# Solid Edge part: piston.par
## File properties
Author: Vicky Raina
Template: normal.par
Last saved by: Robert a Rhodes jr
Revision: 8
Application: Solid Edge
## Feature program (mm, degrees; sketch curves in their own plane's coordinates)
sketch for "unnamed RevolvedProtrusion 1" plane through (0, 0, 0) normal (0, -1, 0) x-axis (1, 0, 0)
  line (0, 27.2252) -> (0, 16)
  line (0, 16) -> (37, 16)
  line (37, 16) -> (37, -4)
  line (37, -4) -> (38.5, -4)
  line (38.5, -4) -> (38.5, -34)
  line (38.5, -34) -> (37, -34)
  line (37, -34) -> (37, -46)
  line (46.5, -46) -> (37, -46)
  line (46.5, -41) -> (46.5, -46)
  line (42.5, -41) -> (46.5, -41)
  line (42.5, -39) -> (42.5, -41)
  line (46.5, -39) -> (42.5, -39)
  line (46.5, 0) -> (46.5, -39)
  line (42.5, 0) -> (46.5, 0)
  line (42.5, 3) -> (42.5, 0)
  line (46.5, 3) -> (42.5, 3)
  line (46.5, 5) -> (46.5, 3)
  line (42.5, 5) -> (46.5, 5)
  line (42.5, 8) -> (42.5, 5)
  line (46.5, 8) -> (42.5, 8)
  line (46.5, 10) -> (46.5, 8)
  line (42.5, 10) -> (46.5, 10)
  line (42.5, 13) -> (42.5, 10)
  line (46.5, 13) -> (42.5, 13)
  line (46.5, 15) -> (46.5, 13)
  line (42.5, 15) -> (46.5, 15)
  line (42.5, 18) -> (42.5, 15)
  line (46.5, 18) -> (42.5, 18)
  line (46.5, 20) -> (46.5, 18)
  arc centre (-5.5431, -161.6935) radius 189 from (0, 27.2252) to (46.5, 20) cw
revolve "unnamed RevolvedProtrusion 1" add full turn 360 deg
sketch for "unnamed Protrusion 1" plane through (0, 25, 0) normal (0, -1, 0) x-axis (1, 0, 0)
  circle centre (0, -19.5) radius 19
extrude "unnamed Protrusion 1" add through along -normal
mirror "unnamed Mirror 1" of "unnamed Protrusion 1" about plane through (0, 0, 0) normal (0, -1, 0)
extrude "unnamed Protrusion 2" add through
sketch for "unnamed RevolvedCutout 1" plane through (0, 0, 0) normal (1, 0, 0) x-axis (0, 1, 0)
revolve "unnamed RevolvedCutout 1" cut finite 360 deg about sketch line (-52.4217, -19) -> (59.5434, -19)
mirror "unnamed Mirror 2" of "unnamed RevolvedCutout 1"
pattern "unnamed Pattern 1"
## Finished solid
Body 1: solid body, 42 faces, 58 edges, 16 vertices.
  Faces by surface: cylinder 21, plane 20, torus 1
  Edges by curve: circle 40, intersection 10, line 8
Bounding box of the edges (mm; curved faces can reach further): 93.000 x 93.000 x 66.000, from (-46.5, -46.5, -46) to (46.5, 46.5, 20).
Cylindrical faces by radius (mm): R10 x2, R15 x2, R19 x2, R37 x2, R38.5 x2, R42.5 x5, R46.5 x6
Toroidal faces (ring radius, tube radius in mm): R-5.5431 r189 x1
Planar faces by outward normal: +y 2, +z 7, -y 2, -z 9
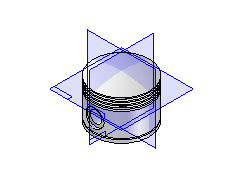
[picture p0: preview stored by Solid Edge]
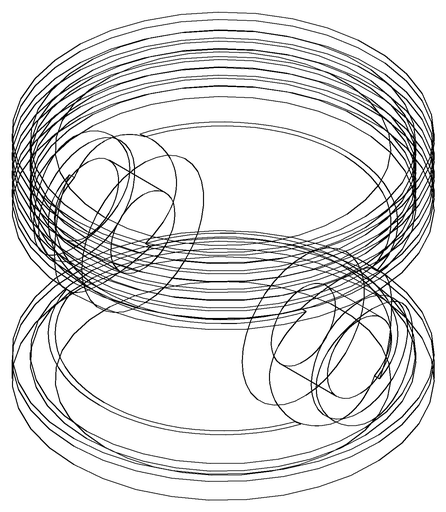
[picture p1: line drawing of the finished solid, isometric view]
